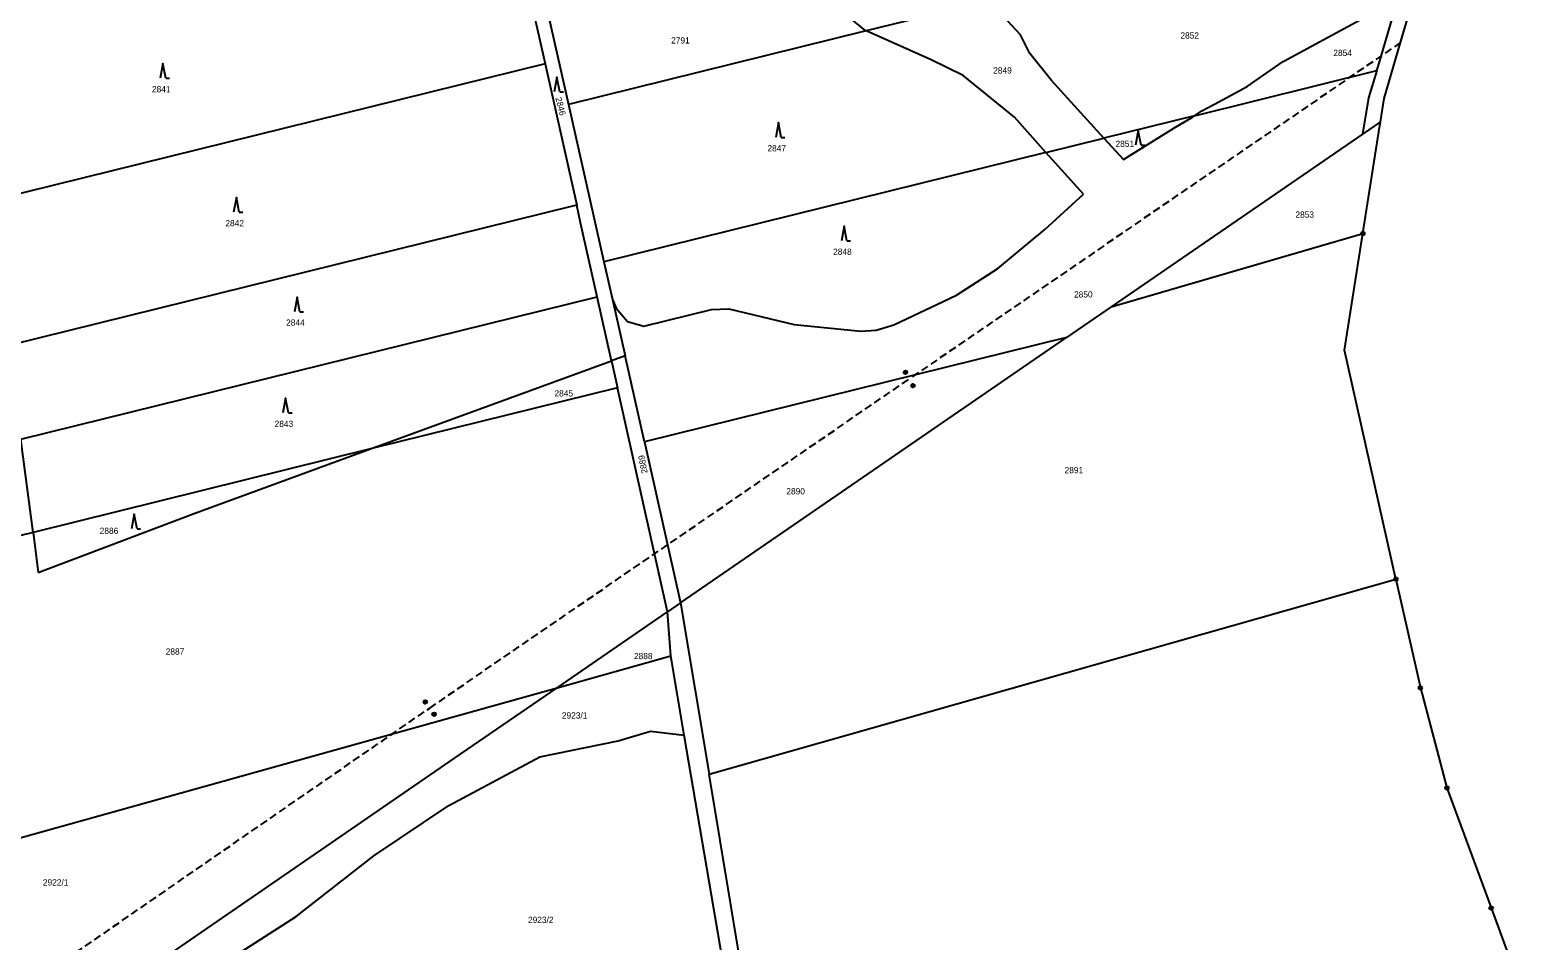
# Model space of a CAD drawing. Extents: x -606517 to -602431, y -1183120 to -1179397.
# Drawn here: x -603949.5 to -603539.1, y -1182112 to -1181863.9 of the extents above; entities that cross this region are included whole.
import ezdxf
from ezdxf.enums import TextEntityAlignment as Align

# ---------------------------------------------------------------- set-up
doc = ezdxf.new("R2010")
doc.units = 0
doc.header["$LTSCALE"] = 0.68
doc.linetypes.add('MEDIUM_DASHED', pattern=[4.5, 3, -1.5])
for name, color, linetype, lineweight in [('1', 7, 'Continuous', 25), ('3', 7, 'Continuous', 25), ('6', 7, 'Continuous', 25), ('8', 7, 'Continuous', 25)]:
    doc.layers.add(name, color=color, linetype=linetype, lineweight=lineweight)
doc.layers.add('2', color=7, linetype='Continuous')

msp = doc.modelspace()

# ---------------------------------------------------------------- linework, layer by layer
at = {"layer": '1'}
for p, q in [((-603817.13, -1181838.29), (-603809.36, -1181873.04)), ((-603582.56, -1181873.79), (-603573.23, -1181842.14)), ((-603576.48, -1181867.3), (-603569.1, -1181842.26)), ((-603722.06, -1181864.07), (-603733.83, -1181854.46)), ((-603686.91, -1181855.45), (-603721.96, -1181864.12)), ((-603608.4, -1181872.48), (-603577.58, -1181855.74)), ((-603679.98, -1181865.19), (-603683.5, -1181861.33)), ((-603721.96, -1181864.12), (-603802.97, -1181884.16)), ((-603721.96, -1181864.12), (-603722.06, -1181864.07)), ((-603704.22, -1181871.96), (-603721.96, -1181864.12)), ((-603677.42, -1181870.3), (-603679.98, -1181865.19)), ((-603580.96, -1181882.53), (-603576.48, -1181867.3)), ((-603695.58, -1181876.24), (-603704.22, -1181871.96)), ((-603671.47, -1181877.62), (-603677.42, -1181870.3)), ((-603809.36, -1181873.04), (-603977.8, -1181914.71)), ((-603809.36, -1181873.04), (-603800.75, -1181911.58)), ((-603681.6, -1181887.64), (-603695.58, -1181876.24)), ((-603632.59, -1181887.22), (-603582.91, -1181874.93)), ((-603618.19, -1181879.23), (-603608.4, -1181872.48)), ((-603582.91, -1181874.93), (-603585.2, -1181882.33)), ((-603582.91, -1181874.93), (-603582.56, -1181873.79)), ((-603657.24, -1181893.32), (-603671.47, -1181877.62)), ((-603627.08, -1181884.03), (-603618.19, -1181879.23)), ((-603802.97, -1181884.16), (-603793.35, -1181927)), ((-603630.58, -1181885.84), (-603627.08, -1181884.03)), ((-603585.2, -1181882.33), (-603586.84, -1181892.2)), ((-603581.95, -1181888.84), (-603580.96, -1181882.53)), ((-603673.02, -1181897.23), (-603681.6, -1181887.64)), ((-603632.59, -1181887.22), (-603657.24, -1181893.32)), ((-603638.23, -1181890.61), (-603633.11, -1181887.58)), ((-603633.11, -1181887.58), (-603632.59, -1181887.22)), ((-603632.59, -1181887.22), (-603630.58, -1181885.84)), ((-603586.84, -1181892.2), (-603655.23, -1181939.25)), ((-603651.93, -1181899.18), (-603638.23, -1181890.61)), ((-603581.95, -1181888.84), (-603586.84, -1181892.2)), ((-603582.11, -1181889.88), (-603581.95, -1181888.84)), ((-603673.02, -1181897.23), (-603657.24, -1181893.32)), ((-603657.24, -1181893.32), (-603651.93, -1181899.18)), ((-603673.02, -1181897.23), (-603793.35, -1181927)), ((-603662.83, -1181908.62), (-603673.02, -1181897.23)), ((-603673.3, -1181918.17), (-603662.83, -1181908.62)), ((-603801.57, -1181911.78), (-603955.32, -1181949.83)), ((-603800.75, -1181911.58), (-603801.57, -1181911.78)), ((-603799.68, -1181916.35), (-603800.75, -1181911.58)), ((-603795.17, -1181936.53), (-603799.68, -1181916.35)), ((-603686.14, -1181928.86), (-603673.3, -1181918.17)), ((-603655.23, -1181939.25), (-603586.73, -1181919.3)), ((-603793.35, -1181927), (-603791.05, -1181937.24)), ((-603697.4, -1181936.06), (-603686.14, -1181928.86)), ((-603952.03, -1181975.35), (-603795.17, -1181936.53)), ((-603791.28, -1181953.95), (-603795.17, -1181936.53)), ((-603791.05, -1181937.24), (-603787.6, -1181952.61)), ((-603791.05, -1181937.24), (-603790.04, -1181939.68)), ((-603714.41, -1181944.14), (-603697.4, -1181936.06)), ((-603790.04, -1181939.68), (-603786.9, -1181943.25)), ((-603782.52, -1181944.53), (-603764.09, -1181939.99)), ((-603764.09, -1181939.99), (-603759.38, -1181939.81)), ((-603759.38, -1181939.81), (-603741.52, -1181944.05)), ((-603655.23, -1181939.25), (-603667.38, -1181947.61)), ((-603786.9, -1181943.25), (-603782.52, -1181944.53)), ((-603741.52, -1181944.05), (-603723.43, -1181945.89)), ((-603723.43, -1181945.89), (-603719.19, -1181945.61)), ((-603719.19, -1181945.61), (-603714.41, -1181944.14)), ((-603667.38, -1181947.61), (-603782.33, -1181976.05)), ((-603772.48, -1182019.91), (-603667.38, -1181947.61)), ((-603856.87, -1181978), (-603791.28, -1181953.95)), ((-603787.6, -1181952.61), (-603791.28, -1181953.95)), ((-603791.28, -1181953.95), (-603789.62, -1181961.36)), ((-603782.33, -1181976.05), (-603787.6, -1181952.61)), ((-603577.73, -1182013.45), (-603591.71, -1181951.06)), ((-603789.62, -1181961.36), (-603856.87, -1181978)), ((-603776, -1182022.33), (-603789.62, -1181961.36)), ((-603948.75, -1182000.74), (-603952.03, -1181975.35)), ((-603856.87, -1181978), (-603948.75, -1182000.74)), ((-603905.12, -1181995.69), (-603856.87, -1181978)), ((-603782.33, -1181976.05), (-603772.48, -1182019.91)), ((-603947.34, -1182011.69), (-603905.12, -1181995.69)), ((-603948.75, -1182000.74), (-603977.63, -1182007.89)), ((-603948.75, -1182000.74), (-603947.34, -1182011.69)), ((-603764.73, -1182066.57), (-603577.73, -1182013.45)), ((-603577.73, -1182013.45), (-603571.09, -1182043.09)), ((-603772.48, -1182019.91), (-603776, -1182022.33)), ((-603772.48, -1182019.91), (-603764.73, -1182066.57)), ((-603806.1, -1182043.04), (-603776, -1182022.33)), ((-603775.12, -1182034.38), (-603776, -1182022.33)), ((-603771.46, -1182055.96), (-603775.12, -1182034.38)), ((-603974.34, -1182090.06), (-603806.1, -1182043.04)), ((-603571.09, -1182043.09), (-603563.85, -1182070.33)), ((-603758.46, -1182132.57), (-603771.46, -1182055.96)), ((-603940.43, -1182135.44), (-603832.25, -1182061.03)), ((-603750.34, -1182153.23), (-603764.73, -1182066.57)), ((-603563.85, -1182070.33), (-603551.81, -1182103.05)), ((-603551.81, -1182103.05), (-603539.1, -1182137.59))]:
    msp.add_line(p, q, dxfattribs=at)
for points in [[(-603812.37, -1181842.31), (-603807.67, -1181863.24), (-603802.97, -1181884.16)], [(-603591.71, -1181951.06), (-603586.73, -1181919.3), (-603582.11, -1181889.88)], [(-603832.25, -1182061.03), (-603806.1, -1182043.04), (-603775.12, -1182034.38)], [(-603938.97, -1182146.78), (-603927.81, -1182139.04), (-603898.15, -1182118.91), (-603877.16, -1182105.34), (-603855.97, -1182088.89), (-603835.54, -1182075.14), (-603810.75, -1182061.87), (-603789.5, -1182057.56), (-603780.67, -1182054.87), (-603771.46, -1182055.96)]]:
    msp.add_lwpolyline(points, dxfattribs=at)
at = {"layer": '3'}
for p, q in [((-603912.63, -1181876.99), (-603911.634, -1181876.99)), ((-603805.37, -1181880.73), (-603804.374, -1181880.73)), ((-603745.08, -1181893.1), (-603744.084, -1181893.1)), ((-603647.11, -1181895.24), (-603646.114, -1181895.24)), ((-603892.64, -1181913.52), (-603891.644, -1181913.52)), ((-603727.2, -1181921.29), (-603726.204, -1181921.29)), ((-603876.11, -1181940.6), (-603875.114, -1181940.6)), ((-603879.24, -1181968.17), (-603878.244, -1181968.17)), ((-603920.45, -1181999.79), (-603919.454, -1181999.79))]:
    msp.add_line(p, q, dxfattribs=at)
for points in [[(-603912.63, -1181876.99), (-603913.38, -1181872.99), (-603914.13, -1181876.99)], [(-603805.37, -1181880.73), (-603806.12, -1181876.73), (-603806.87, -1181880.73)], [(-603745.08, -1181893.1), (-603745.83, -1181889.1), (-603746.58, -1181893.1)], [(-603647.11, -1181895.24), (-603647.86, -1181891.24), (-603648.61, -1181895.24)], [(-603892.64, -1181913.52), (-603893.39, -1181909.52), (-603894.14, -1181913.52)], [(-603727.2, -1181921.29), (-603727.95, -1181917.29), (-603728.7, -1181921.29)], [(-603876.11, -1181940.6), (-603876.86, -1181936.6), (-603877.61, -1181940.6)], [(-603879.24, -1181968.17), (-603879.99, -1181964.17), (-603880.74, -1181968.17)], [(-603920.45, -1181999.79), (-603921.2, -1181995.79), (-603921.95, -1181999.79)]]:
    msp.add_lwpolyline(points, dxfattribs=at)
at = {"layer": '6', "linetype": 'MEDIUM_DASHED'}
for p in [(-603576.48, -1181867.3), (-603840.76, -1182048.58)]:
    msp.add_line(p, (-603710.23, -1181958.93), dxfattribs=at)
msp.add_lwpolyline([(-604552.48, -1182329.87), (-604349.28, -1182265.78), (-604199.08, -1182218.47), (-603994.94, -1182155.23), (-603840.76, -1182048.58)], dxfattribs=at)
at = {"layer": '6'}
for centre, radius in [((-603711.2634, -1181957.1199), 0.5), ((-603711.2634, -1181957.1199), 0.4), ((-603711.2634, -1181957.1199), 0.3), ((-603711.2634, -1181957.1199), 0.2), ((-603711.2634, -1181957.1199), 0.1), ((-603709.2034, -1181960.7499), 0.5), ((-603709.2034, -1181960.7499), 0.4), ((-603709.2034, -1181960.7499), 0.3), ((-603709.2034, -1181960.7499), 0.2), ((-603709.2034, -1181960.7499), 0.1), ((-603841.9634, -1182046.9099), 0.5), ((-603841.9634, -1182046.9099), 0.4), ((-603841.9634, -1182046.9099), 0.3), ((-603841.9634, -1182046.9099), 0.2), ((-603841.9634, -1182046.9099), 0.1), ((-603839.5634, -1182050.2599), 0.5), ((-603839.5634, -1182050.2599), 0.4), ((-603839.5634, -1182050.2599), 0.3), ((-603839.5634, -1182050.2599), 0.2), ((-603839.5634, -1182050.2599), 0.1)]:
    msp.add_circle(centre, radius, dxfattribs=at)
at = {"layer": '8'}
for centre, radius in [((-603586.73, -1181919.2999), 0.5), ((-603586.73, -1181919.2999), 0.0303), ((-603577.73, -1182013.4499), 0.5), ((-603577.73, -1182013.4499), 0.0303), ((-603571.09, -1182043.0899), 0.5), ((-603571.09, -1182043.0899), 0.0303), ((-603563.85, -1182070.3299), 0.5), ((-603563.85, -1182070.3299), 0.0303), ((-603551.81, -1182103.0499), 0.5), ((-603551.81, -1182103.0499), 0.0303)]:
    msp.add_circle(centre, radius, dxfattribs=at)

# ---------------------------------------------------------------- texts
at = {"layer": '2'}
for s, p in [('2791', (-603775.05, -1181867.535)), ('2852', (-603636.4, -1181866.185)), ('2854', (-603594.77, -1181870.955)), ('2849', (-603687.38, -1181875.715)), ('2841', (-603916.38, -1181880.815)), ('2847', (-603748.83, -1181896.925)), ('2851', (-603654.07, -1181895.725)), ('2842', (-603896.39, -1181917.345)), ('2853', (-603605.09, -1181914.995)), ('2848', (-603730.95, -1181925.115)), ('2850', (-603665.36, -1181936.735)), ('2844', (-603879.86, -1181944.425)), ('2845', (-603806.81, -1181963.695)), ('2843', (-603882.99, -1181971.995)), ('2891', (-603667.93, -1181984.605)), ('2890', (-603743.68, -1181990.375)), ('2886', (-603930.6, -1182001.145)), ('2887', (-603912.63, -1182034.035)), ('2888', (-603785.16, -1182035.265))]:
    msp.add_text(s, height=1.7, dxfattribs=at).set_placement(p)
for s, rotation, p in [('2846', 284, (-603806.552, -1181882.402)), ('2889', 101, (-603781.422, -1181984.498))]:
    msp.add_text(s, height=1.7, rotation=rotation, dxfattribs=at).set_placement(p)
for s, p in [('2923/1', (-603801.31, -1182051.445)), ('2922/1', (-603942.59, -1182096.935)), ('2923/2', (-603810.53, -1182107.135))]:
    msp.add_text(s, height=1.7, dxfattribs=at).set_placement(p, align=Align.CENTER)

doc.saveas('drawing.dxf')
